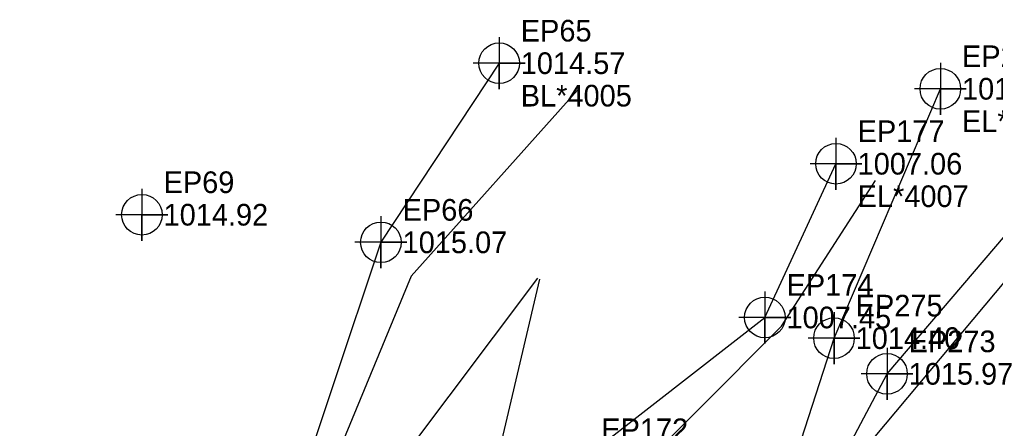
# Model space of a CAD drawing. Extents: x 1382561 to 1383039, y 884068 to 884307.
# Drawn here: x 1382751.3 to 1382864, y 884246 to 884293.2 of the extents above; entities that cross this region are included whole.
import ezdxf

# ---------------------------------------------------------------- set-up
doc = ezdxf.new("R2010")
doc.units = 0
for name, color, linetype in [('Exist DTM Breakline', 7, 'Continuous'), ('Exist DTM Breakline Cogo Comment', 7, 'Continuous'), ('Exist DTM Breakline Cogo Elevation', 7, 'Continuous'), ('Exist DTM Breakline Cogo Number', 7, 'Continuous'), ('Exist DTM Breakline Cogo Point CELL', 7, 'Continuous'), ('Exist DTM Breakline Underwater', 7, 'Continuous'), ('Exist DTM Breakline Underwater Cogo Comment', 7, 'Continuous'), ('Exist DTM Breakline Underwater Cogo Elevation', 7, 'Continuous'), ('Exist DTM Breakline Underwater Cogo Number', 7, 'Continuous'), ('Exist DTM Breakline Underwater Cogo Point CELL', 7, 'Continuous'), ('Exist DTM Regular Point CELL', 7, 'Continuous'), ('Exist DTM Regular Point Cogo Elevation', 7, 'Continuous'), ('Exist DTM Regular Point Cogo Number', 7, 'Continuous'), ('Exist Hydro Stream or Body of Water', 7, 'Continuous')]:
    doc.layers.add(name, color=color, linetype=linetype)

msp = doc.modelspace()

# ---------------------------------------------------------------- linework, layer by layer
at = {"layer": 'Exist DTM Breakline'}
msp.add_line((1382845.6099, 884239.6486), (1382877.4407, 884277.6733), dxfattribs=at)
for points in [[(1382806.7045, 884288.1336), (1382793.0575, 884267.4591), (1382781.8725, 884234.0918), (1382778.997, 884218.196), (1382773.7671, 884215.476), (1382722.2214, 884211.0337), (1382668.872, 884203.9756), (1382615.627, 884202.5184), (1382567.5113, 884196.1242)], [(1382836.5882, 884229.1511), (1382845.3839, 884256.4006), (1382857.665, 884285.1804)], [(1382841.0523, 884232.5474), (1382851.5055, 884252.2797), (1382873.9304, 884278.5226)]]:
    msp.add_lwpolyline(points, dxfattribs=at)
at = {"layer": 'Exist DTM Breakline Cogo Point CELL'}
for points in [[(1382806.7045, 884291.1336), (1382806.7045, 884285.1336), (1382806.7045, 884288.1336), (1382809.7045, 884288.1336), (1382803.7045, 884288.1336)], [(1382857.665, 884288.1804), (1382857.665, 884282.1804), (1382857.665, 884285.1804), (1382860.665, 884285.1804), (1382854.665, 884285.1804)], [(1382793.0575, 884270.4591), (1382793.0575, 884264.4591), (1382793.0575, 884267.4591), (1382796.0575, 884267.4591), (1382790.0575, 884267.4591)], [(1382845.3839, 884259.4006), (1382845.3839, 884253.4006), (1382845.3839, 884256.4006), (1382848.3839, 884256.4006), (1382842.3839, 884256.4006)], [(1382851.5055, 884255.2797), (1382851.5055, 884249.2797), (1382851.5055, 884252.2797), (1382854.5055, 884252.2797), (1382848.5055, 884252.2797)]]:
    msp.add_lwpolyline(points, dxfattribs=at)
for centre in [(1382806.7045, 884288.1336), (1382857.665, 884285.1804), (1382793.0575, 884267.4591), (1382845.3839, 884256.4006), (1382851.5055, 884252.2797)]:
    msp.add_circle(centre, 2.344, dxfattribs=at)
at = {"layer": 'Exist DTM Breakline Underwater'}
msp.add_lwpolyline([(1382688.3783, 884086.9383), (1382699.504, 884112.5821), (1382721.2073, 884133.5617), (1382743.6214, 884142.6712), (1382769.5658, 884160.0329), (1382785.1067, 884174.8132), (1382789.3291, 884181.9565), (1382809.982, 884219.9732), (1382816.0046, 884242.1273), (1382837.3981, 884258.7844), (1382845.6113, 884276.5289)], dxfattribs=at)
at = {"layer": 'Exist DTM Breakline Underwater Cogo Point CELL'}
for points in [[(1382845.6113, 884279.5289), (1382845.6113, 884273.5289), (1382845.6113, 884276.5289), (1382848.6113, 884276.5289), (1382842.6113, 884276.5289)], [(1382837.3981, 884261.7844), (1382837.3981, 884255.7844), (1382837.3981, 884258.7844), (1382840.3981, 884258.7844), (1382834.3981, 884258.7844)]]:
    msp.add_lwpolyline(points, dxfattribs=at)
for centre in [(1382845.6113, 884276.5289), (1382837.3981, 884258.7844)]:
    msp.add_circle(centre, 2.344, dxfattribs=at)
at = {"layer": 'Exist DTM Regular Point CELL'}
msp.add_lwpolyline([(1382765.4479, 884273.6439), (1382765.4479, 884267.6439), (1382765.4479, 884270.6439), (1382768.4479, 884270.6439), (1382762.4479, 884270.6439)], dxfattribs=at)
msp.add_circle((1382765.4479, 884270.6439), 2.344, dxfattribs=at)
at = {"layer": 'Exist Hydro Stream or Body of Water'}
for points in [[(1382815.7469, 884285.0295), (1382796.5538, 884263.5381), (1382784.2894, 884233.9786), (1382781.1386, 884206.3096), (1382772.3397, 884180.9543), (1382766.7799, 884172.9781), (1382757.421, 884165.3571), (1382736.1951, 884155.0402), (1382706.3401, 884136.6072), (1382689.3837, 884112.6314), (1382676.096, 884092.4493)], [(1382697.0874, 884084.7019), (1382707.0296, 884107.5273), (1382718.101, 884120.6229), (1382747.1797, 884135.9958), (1382776.4132, 884151.3238), (1382791.7634, 884168.9711), (1382798.6691, 884182.5745), (1382820.5432, 884217.5751), (1382820.037, 884238.4145), (1382839.3094, 884257.7694), (1382850.1603, 884274.5827)], [(1382811.148, 884263.3209), (1382795.7798, 884242.8831), (1382794.8118, 884220.542)], [(1382811.3728, 884263.1874), (1382805.484, 884238.1799), (1382794.8471, 884220.9683)]]:
    msp.add_lwpolyline(points, dxfattribs=at)

# ---------------------------------------------------------------- texts
at = {"layer": 'Exist DTM Breakline Cogo Comment'}
for s, p in [('BL*4005', (1382809.2045, 884283.1336)), ('EL*4005', (1382860.165, 884280.1804))]:
    msp.add_text(s, height=2.5, dxfattribs=at).set_placement(p)
at = {"layer": 'Exist DTM Breakline Cogo Elevation'}
for s, p in [('1014.57', (1382809.2045, 884286.8836)), ('1013.03', (1382860.165, 884283.9304)), ('1015.07', (1382795.5575, 884266.2091)), ('1014.40', (1382847.8839, 884255.1506)), ('1015.97', (1382854.0055, 884251.0297))]:
    msp.add_text(s, height=2.5, dxfattribs=at).set_placement(p)
at = {"layer": 'Exist DTM Breakline Cogo Number'}
for s, p in [('EP65', (1382809.2045, 884290.6336)), ('EP276', (1382860.165, 884287.6804)), ('EP66', (1382795.5575, 884269.9591)), ('EP275', (1382847.8839, 884258.9006)), ('EP273', (1382854.0055, 884254.7797))]:
    msp.add_text(s, height=2.5, dxfattribs=at).set_placement(p)
at = {"layer": 'Exist DTM Breakline Underwater Cogo Comment'}
msp.add_text('EL*4007', height=2.5, dxfattribs=at).set_placement((1382848.1113, 884271.5289))
at = {"layer": 'Exist DTM Breakline Underwater Cogo Elevation'}
for s, p in [('1007.06', (1382848.1113, 884275.2789)), ('1007.45', (1382839.8981, 884257.5344))]:
    msp.add_text(s, height=2.5, dxfattribs=at).set_placement(p)
at = {"layer": 'Exist DTM Breakline Underwater Cogo Number'}
for s, p in [('EP177', (1382848.1113, 884279.0289)), ('EP174', (1382839.8981, 884261.2844)), ('EP172', (1382818.5046, 884244.6273))]:
    msp.add_text(s, height=2.5, dxfattribs=at).set_placement(p)
at = {"layer": 'Exist DTM Regular Point Cogo Elevation'}
msp.add_text('1014.92', height=2.5, dxfattribs=at).set_placement((1382767.9479, 884269.3939))
at = {"layer": 'Exist DTM Regular Point Cogo Number'}
msp.add_text('EP69', height=2.5, dxfattribs=at).set_placement((1382767.9479, 884273.1439))

doc.saveas('drawing.dxf')
